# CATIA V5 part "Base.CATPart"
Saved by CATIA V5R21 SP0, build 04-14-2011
Part number: Base
Definition: Base
Nomenclature: Base
Source: Unknown
Bounding box of the stored display mesh (mm): x -5.915 to 5.915, y -0.8 to 4.4, z -5 to 5
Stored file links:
  C:\Users\beatr\OneDrive\Documents\UNB\2026_1\Pi1\Componentes eletronicos\Base.CATPart
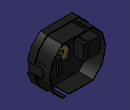
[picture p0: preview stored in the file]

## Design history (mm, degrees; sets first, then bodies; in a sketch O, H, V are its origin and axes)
Body1 "Sólido1" (main body)
  Solid1: solid without history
